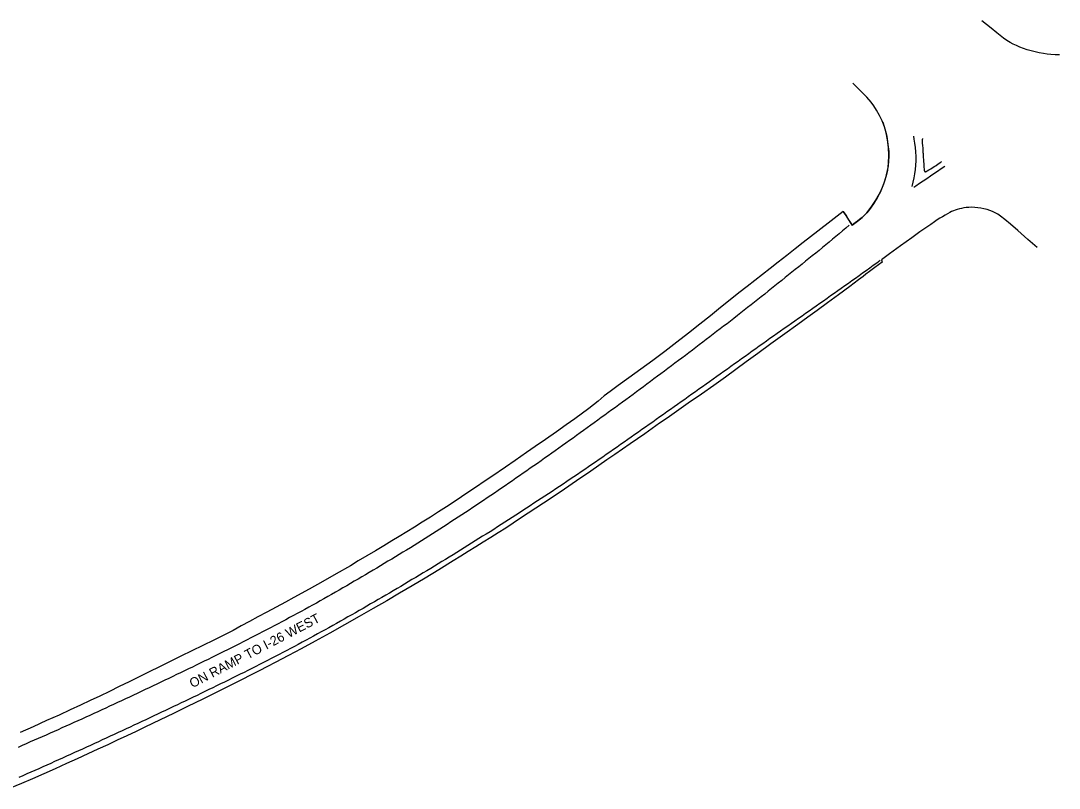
# Model space of a CAD drawing. Extents: x 1961683 to 1977751, y 798292 to 805767.
# Drawn here: x 1970784 to 1971379, y 802511 to 802951 of the extents above; entities that cross this region are included whole.
import ezdxf

# ---------------------------------------------------------------- set-up
doc = ezdxf.new("R2010")
doc.units = 0
for name, color, linetype in [('RD_EX_Conc', 7, 'Continuous'), ('RD_EX_Road', 7, 'Continuous'), ('RD_EX_Road_Paint', 7, 'Continuous'), ('RD_TX_RoadID', 7, 'Continuous')]:
    doc.layers.add(name, color=color, linetype=linetype)

msp = doc.modelspace()

# ---------------------------------------------------------------- linework, layer by layer
at = {"layer": 'RD_EX_Conc'}
msp.add_lwpolyline([(1971300.79, 802883.01), (1971300.74, 802882.82), (1971300.67, 802882.28), (1971300.67, 802881.48), (1971300.72, 802880.37), (1971300.82, 802878.97), (1971300.93, 802877.5), (1971301.05, 802876.05), (1971301.11, 802875.12), (1971301.12, 802874.54), (1971301.22, 802872.95), (1971301.41, 802870.36), (1971301.56, 802868.15), (1971301.67, 802866.55), (1971301.74, 802865.56), (1971301.79, 802865.1), (1971301.84, 802864.78), (1971301.91, 802864.53), (1971301.99, 802864.33), (1971302.04, 802864.25), (1971302.1, 802864.19), (1971302.16, 802864.13), (1971302.21, 802864.09), (1971302.28, 802864.05), (1971302.35, 802864.03), (1971302.45, 802864.03), (1971302.57, 802864.04), (1971302.71, 802864.07), (1971302.91, 802864.14), (1971303.55, 802864.46), (1971304.5, 802865.03), (1971305.65, 802865.75), (1971306.91, 802866.57), (1971307.88, 802867.2), (1971308.6, 802867.67), (1971309.72, 802868.46), (1971311.27, 802869.57), (1971311.66, 802869.84)], dxfattribs=at)
at = {"layer": 'RD_EX_Road'}
for points in [[(1971379.24, 802930.98), (1971376.83, 802931.04), (1971374.46, 802931.18), (1971372.29, 802931.4), (1971370.11, 802931.73), (1971367.74, 802932.19), (1971365.33, 802932.74), (1971363.04, 802933.33), (1971360.82, 802933.99), (1971358.63, 802934.73), (1971356.56, 802935.53), (1971354.67, 802936.33), (1971352.85, 802937.2), (1971350.98, 802938.21), (1971349.11, 802939.36), (1971347.26, 802940.66), (1971345.37, 802942.1), (1971343.34, 802943.69), (1971340.17, 802946.25), (1971334.83, 802950.59)], [(1971255.41, 802841.16), (1971257.06, 802838.99), (1971258.68, 802836.32), (1971260.51, 802833.29), (1971263.59, 802835.69), (1971266.19, 802837.84), (1971268.87, 802840.52), (1971271.41, 802843.68), (1971274.17, 802847.67), (1971276.68, 802852.22), (1971278.67, 802857.01), (1971280.02, 802861.34), (1971280.88, 802864.98), (1971281.4, 802868.88), (1971281.56, 802873.45), (1971281.32, 802877.95), (1971280.72, 802882.32), (1971279.93, 802886.26), (1971278.98, 802889.7), (1971277.63, 802893.22), (1971276.12, 802896.28), (1971274.52, 802899.26), (1971272.97, 802901.88), (1971271.32, 802904), (1971268.85, 802906.71), (1971263.87, 802911.8), (1971260.98, 802914.75)], [(1971278, 802892.43), (1971278.82, 802890), (1971279.62, 802887.26), (1971280.32, 802884.33), (1971280.86, 802881.34), (1971281.23, 802878.39), (1971281.45, 802875.53), (1971281.51, 802872.77), (1971281.39, 802870.07), (1971281.1, 802867.4), (1971280.65, 802864.76), (1971280.08, 802862.2), (1971279.42, 802859.76), (1971278.66, 802857.39), (1971277.75, 802854.98), (1971276.55, 802852.28), (1971274.89, 802849.05), (1971272.82, 802845.54), (1971270.42, 802842.42), (1971268.87, 802840.52), (1971267.65, 802839.2), (1971266.19, 802837.84), (1971264.75, 802836.61), (1971263.59, 802835.69), (1971262.31, 802834.71), (1971260.51, 802833.29), (1971257.06, 802838.99), (1971255.41, 802841.16), (1971248.48, 802835.94), (1971240.82, 802830.01), (1971236.7, 802826.78), (1971232.35, 802823.36), (1971227.79, 802819.77), (1971223, 802816), (1971218.19, 802812.21), (1971213.55, 802808.57), (1971209.08, 802805.08), (1971204.78, 802801.73), (1971200.4, 802798.3), (1971195.65, 802794.55), (1971190.56, 802790.48), (1971185.11, 802786.09), (1971179.32, 802781.44), (1971173.2, 802776.58), (1971166.76, 802771.51), (1971160, 802766.24), (1971153.09, 802760.92), (1971146.22, 802755.75), (1971139.38, 802750.72), (1971132.58, 802745.83), (1971126.5, 802741.46), (1971121.79, 802738.01), (1971118.46, 802735.47), (1971114.92, 802732.46), (1971109.64, 802728.3), (1971101.63, 802722.36), (1971096.66, 802718.8), (1971091.07, 802714.85), (1971084.86, 802710.53), (1971078.87, 802706.39), (1971073.98, 802703), (1971067.46, 802698.48), (1971061.95, 802694.69), (1971054.06, 802689.36), (1971049.57, 802686.34), (1971045.17, 802683.38), (1971040.85, 802680.47), (1971036.62, 802677.62), (1971032.36, 802674.78), (1971027.98, 802671.9), (1971023.47, 802668.97), (1971018.84, 802666.01), (1971014.2, 802663.08), (1971009.67, 802660.25), (1971005.27, 802657.53), (1971000.98, 802654.91), (1970996.65, 802652.29), (1970992.11, 802649.55), (1970987.36, 802646.71), (1970982.41, 802643.75), (1970977.51, 802640.84), (1970972.95, 802638.14), (1970964.83, 802633.38), (1970957.24, 802629.03), (1970949.38, 802624.65), (1970940.64, 802619.88), (1970935.71, 802617.22), (1970930.42, 802614.38), (1970925.06, 802611.5), (1970919.96, 802608.75), (1970915.1, 802606.11), (1970910.48, 802603.6), (1970905.74, 802601.06), (1970900.5, 802598.35), (1970894.75, 802595.46), (1970888.51, 802592.4), (1970882.07, 802589.28), (1970875.78, 802586.2), (1970869.62, 802583.17), (1970863.6, 802580.19), (1970857.69, 802577.26), (1970851.86, 802574.38), (1970846.12, 802571.56), (1970840.46, 802568.79), (1970834.86, 802566.08), (1970829.3, 802563.4), (1970823.77, 802560.77), (1970818.27, 802558.17), (1970812.46, 802555.47), (1970806, 802552.5), (1970798.89, 802549.28), (1970791.13, 802545.79), (1970783.74, 802542.5)], [(1971366.46, 802820.56), (1971361.23, 802825.21), (1971355.45, 802830.32), (1971351.3, 802833.95), (1971348, 802836.69), (1971345.59, 802838.5), (1971343.94, 802839.6), (1971342.93, 802840.24), (1971342.07, 802840.68), (1971340.9, 802841.23), (1971339.46, 802841.8), (1971337.8, 802842.34), (1971336.05, 802842.81), (1971334.34, 802843.15), (1971332.6, 802843.4), (1971330.78, 802843.56), (1971328.98, 802843.61), (1971327.3, 802843.56), (1971325.76, 802843.42), (1971324.43, 802843.25), (1971323.2, 802843.03), (1971321.97, 802842.75), (1971320.78, 802842.43), (1971319.63, 802842.05), (1971318.55, 802841.62), (1971317.52, 802841.13), (1971316.44, 802840.56), (1971315.17, 802839.89), (1971313.75, 802839.12), (1971312.22, 802838.25), (1971310.71, 802837.34), (1971309.32, 802836.43), (1971307.72, 802835.33), (1971305.53, 802833.85), (1971302.75, 802831.92), (1971299.34, 802829.48), (1971294.72, 802826.17), (1971288.3, 802821.6), (1971281.91, 802816.99), (1971277.33, 802813.57), (1971277.64, 802812.13)], [(1971277.64, 802812.13), (1971273.49, 802809.08), (1971270.49, 802806.84), (1971268.34, 802805.2), (1971266.76, 802803.98), (1971264.21, 802802.02), (1971259.13, 802798.19), (1971252.78, 802793.45), (1971246.39, 802788.79), (1971240.37, 802784.41), (1971235.14, 802780.55), (1971229.44, 802776.36), (1971221.99, 802771.02), (1971213.96, 802765.29), (1971206.51, 802759.88), (1971199.77, 802754.93), (1971193.84, 802750.54), (1971187.95, 802746.24), (1971181.33, 802741.54), (1971174.14, 802736.52), (1971166.54, 802731.24), (1971158.56, 802725.68), (1971154.42, 802722.78), (1971150.19, 802719.81), (1971145.92, 802716.81), (1971141.67, 802713.83), (1971137.44, 802710.87), (1971133.23, 802707.94), (1971128.96, 802704.97), (1971124.55, 802701.91), (1971119.99, 802698.76), (1971115.28, 802695.52), (1971110.68, 802692.36), (1971102.6, 802686.8), (1971095.67, 802682.04), (1971087.94, 802676.85), (1971083.64, 802674.01), (1971079.23, 802671.1), (1971074.87, 802668.22), (1971070.55, 802665.37), (1971066.28, 802662.54), (1971062.03, 802659.74), (1971057.75, 802656.98), (1971053.45, 802654.26), (1971049.13, 802651.57), (1971044.81, 802648.89), (1971040.51, 802646.21), (1971036.22, 802643.52), (1971031.95, 802640.83), (1971023.69, 802635.67), (1971015.91, 802630.99), (1971008.46, 802626.61), (1971001.16, 802622.34), (1970993.78, 802618.06), (1970986.08, 802613.61), (1970978.05, 802609), (1970969.69, 802604.22), (1970961.21, 802599.42), (1970952.8, 802594.78), (1970944.82, 802590.46), (1970937.58, 802586.63), (1970929.94, 802582.66), (1970925.54, 802580.39), (1970920.74, 802577.91), (1970915.81, 802575.38), (1970911, 802572.92), (1970906.31, 802570.54), (1970901.75, 802568.23), (1970897.26, 802565.98), (1970888.37, 802561.57), (1970879.68, 802557.31), (1970871.65, 802553.4), (1970864.06, 802549.73), (1970855.16, 802545.49), (1970850.12, 802543.1), (1970844.82, 802540.61), (1970839.41, 802538.07), (1970833.89, 802535.5), (1970828.26, 802532.88), (1970822.48, 802530.2), (1970816.48, 802527.45), (1970810.28, 802524.62), (1970803.87, 802521.72), (1970797.37, 802518.81), (1970790.9, 802515.98), (1970784.48, 802513.21), (1970778.09, 802510.52)]]:
    msp.add_lwpolyline(points, dxfattribs=at)
at = {"layer": 'RD_EX_Road_Paint'}
for points in [[(1971294.99, 802855.53), (1971295.51, 802857.98), (1971295.99, 802860.43), (1971296.37, 802862.9), (1971296.75, 802865.37), (1971297.01, 802867.86), (1971297.24, 802870.35), (1971297.15, 802872.85), (1971297.06, 802875.34), (1971296.81, 802877.83), (1971296.45, 802880.31), (1971296.08, 802882.78), (1971295.85, 802884.38)], [(1971313.62, 802867.02), (1971311.55, 802865.62), (1971309.48, 802864.22), (1971307.41, 802862.83), (1971305.34, 802861.43), (1971303.27, 802860.03), (1971301.2, 802858.63), (1971299.13, 802857.23), (1971297.06, 802855.84), (1971295.87, 802855.03)], [(1971258.87, 802833.33), (1971256.96, 802831.72), (1971255.06, 802830.1), (1971253.15, 802828.49), (1971251.24, 802826.88), (1971249.32, 802825.28), (1971247.39, 802823.68), (1971245.46, 802822.09), (1971243.53, 802820.5), (1971241.59, 802818.93), (1971239.64, 802817.36), (1971237.69, 802815.8), (1971235.75, 802814.23), (1971233.8, 802812.67), (1971231.85, 802811.11), (1971229.9, 802809.54), (1971227.95, 802807.98), (1971226, 802806.41), (1971224.05, 802804.85), (1971222.1, 802803.29), (1971220.15, 802801.72), (1971218.2, 802800.16), (1971216.25, 802798.6), (1971214.3, 802797.03), (1971212.35, 802795.47), (1971210.4, 802793.91), (1971208.45, 802792.34), (1971206.5, 802790.78), (1971204.55, 802789.22), (1971202.6, 802787.66), (1971200.63, 802786.12), (1971198.66, 802784.58), (1971196.7, 802783.04), (1971194.73, 802781.5), (1971192.76, 802779.96), (1971190.79, 802778.42), (1971188.81, 802776.9), (1971186.82, 802775.39), (1971184.83, 802773.87), (1971182.84, 802772.36), (1971180.85, 802770.84), (1971178.87, 802769.32), (1971176.88, 802767.81), (1971174.9, 802766.29), (1971172.91, 802764.77), (1971170.93, 802763.25), (1971168.94, 802761.73), (1971166.95, 802760.22), (1971164.96, 802758.71), (1971162.96, 802757.21), (1971160.97, 802755.7), (1971158.98, 802754.2), (1971156.98, 802752.69), (1971154.98, 802751.19), (1971152.98, 802749.7), (1971150.97, 802748.21), (1971148.96, 802746.72), (1971146.96, 802745.23), (1971144.95, 802743.74), (1971142.94, 802742.25), (1971140.94, 802740.76), (1971138.94, 802739.27), (1971136.93, 802737.77), (1971134.93, 802736.27), (1971132.93, 802734.78), (1971130.91, 802733.31), (1971128.88, 802731.84), (1971126.86, 802730.38), (1971124.83, 802728.92), (1971122.8, 802727.46), (1971120.78, 802725.99), (1971118.75, 802724.53), (1971116.73, 802723.07), (1971114.71, 802721.59), (1971112.69, 802720.12), (1971110.67, 802718.65), (1971108.65, 802717.17), (1971106.63, 802715.7), (1971104.61, 802714.23), (1971102.58, 802712.77), (1971100.55, 802711.32), (1971098.52, 802709.86), (1971096.48, 802708.41), (1971094.45, 802706.95), (1971092.42, 802705.5), (1971090.39, 802704.05), (1971088.35, 802702.6), (1971086.31, 802701.14), (1971084.28, 802699.69), (1971082.24, 802698.25), (1971080.2, 802696.81), (1971078.14, 802695.39), (1971076.08, 802693.97), (1971074.03, 802692.55), (1971071.97, 802691.13), (1971069.92, 802689.71), (1971067.86, 802688.28), (1971065.81, 802686.86), (1971063.75, 802685.44), (1971061.7, 802684.01), (1971059.64, 802682.59), (1971057.58, 802681.18), (1971055.52, 802679.77), (1971053.45, 802678.37), (1971051.38, 802676.96), (1971049.31, 802675.56), (1971047.23, 802674.18), (1971045.15, 802672.79), (1971043.07, 802671.41), (1971040.99, 802670.03), (1971038.9, 802668.66), (1971036.81, 802667.29), (1971034.71, 802665.92), (1971032.62, 802664.55), (1971030.53, 802663.19), (1971028.43, 802661.83), (1971026.33, 802660.47), (1971024.23, 802659.12), (1971022.13, 802657.77), (1971020.02, 802656.43), (1971017.91, 802655.08), (1971015.8, 802653.74), (1971013.69, 802652.4), (1971011.58, 802651.07), (1971009.45, 802649.76), (1971007.33, 802648.44), (1971005.2, 802647.12), (1971003.08, 802645.81), (1971000.95, 802644.5), (1970998.81, 802643.21), (1970996.66, 802641.93), (1970994.52, 802640.64), (1970992.38, 802639.35), (1970990.24, 802638.07), (1970988.09, 802636.78), (1970985.95, 802635.5), (1970983.8, 802634.22), (1970981.66, 802632.93), (1970979.5, 802631.67), (1970977.34, 802630.41), (1970975.18, 802629.16), (1970973.01, 802627.91), (1970970.85, 802626.66), (1970968.69, 802625.41), (1970966.52, 802624.15), (1970964.36, 802622.9), (1970962.2, 802621.65), (1970960.03, 802620.41), (1970957.85, 802619.18), (1970955.67, 802617.95), (1970953.5, 802616.73), (1970951.32, 802615.5), (1970949.14, 802614.27), (1970946.96, 802613.06), (1970944.76, 802611.86), (1970942.55, 802610.69), (1970940.35, 802609.51), (1970938.15, 802608.33), (1970935.94, 802607.15), (1970933.74, 802605.98), (1970931.53, 802604.8), (1970929.32, 802603.64), (1970927.1, 802602.47), (1970924.89, 802601.31), (1970922.68, 802600.15), (1970920.46, 802599.01), (1970918.23, 802597.86), (1970916.01, 802596.72), (1970913.79, 802595.57), (1970911.56, 802594.43), (1970909.34, 802593.3), (1970907.1, 802592.18), (1970904.86, 802591.06), (1970902.62, 802589.95), (1970900.39, 802588.84), (1970898.15, 802587.73), (1970895.9, 802586.62), (1970893.66, 802585.52), (1970891.42, 802584.41), (1970889.17, 802583.31), (1970886.93, 802582.21), (1970884.69, 802581.11), (1970882.44, 802580.01), (1970880.19, 802578.93), (1970877.93, 802577.86), (1970875.67, 802576.78), (1970873.42, 802575.71), (1970871.16, 802574.62), (1970868.91, 802573.54), (1970866.66, 802572.46), (1970864.4, 802571.38), (1970862.15, 802570.29), (1970859.89, 802569.21), (1970857.64, 802568.13), (1970855.38, 802567.05), (1970853.12, 802565.98), (1970850.87, 802564.91), (1970848.61, 802563.84), (1970846.35, 802562.77), (1970844.08, 802561.71), (1970841.81, 802560.66), (1970839.55, 802559.61), (1970837.28, 802558.57), (1970835.01, 802557.52), (1970832.74, 802556.47), (1970830.47, 802555.42), (1970828.19, 802554.38), (1970825.92, 802553.34), (1970823.65, 802552.3), (1970821.37, 802551.26), (1970819.1, 802550.22), (1970816.82, 802549.19), (1970814.55, 802548.16), (1970812.27, 802547.13), (1970809.99, 802546.11), (1970807.71, 802545.08), (1970805.43, 802544.06), (1970803.14, 802543.04), (1970800.85, 802542.04), (1970798.56, 802541.04), (1970796.27, 802540.04), (1970793.97, 802539.05), (1970791.68, 802538.05), (1970789.39, 802537.04), (1970787.11, 802536.03), (1970784.83, 802535), (1970782.55, 802533.97)], [(1971276.65, 802813.1), (1971274.62, 802811.64), (1971272.59, 802810.18), (1971270.56, 802808.72), (1971268.53, 802807.26), (1971266.5, 802805.8), (1971264.48, 802804.35), (1971262.45, 802802.89), (1971260.41, 802801.43), (1971258.37, 802799.99), (1971256.33, 802798.54), (1971254.29, 802797.1), (1971252.26, 802795.65), (1971250.22, 802794.21), (1971248.17, 802792.77), (1971246.12, 802791.34), (1971244.08, 802789.9), (1971242.03, 802788.47), (1971239.98, 802787.03), (1971237.94, 802785.6), (1971235.89, 802784.16), (1971233.85, 802782.72), (1971231.8, 802781.28), (1971229.76, 802779.84), (1971227.72, 802778.4), (1971225.67, 802776.97), (1971223.63, 802775.53), (1971221.59, 802774.09), (1971219.54, 802772.65), (1971217.5, 802771.21), (1971215.46, 802769.76), (1971213.43, 802768.31), (1971211.39, 802766.86), (1971209.36, 802765.41), (1971207.32, 802763.96), (1971205.29, 802762.51), (1971203.25, 802761.06), (1971201.22, 802759.61), (1971199.18, 802758.16), (1971197.15, 802756.71), (1971195.11, 802755.25), (1971193.08, 802753.8), (1971191.04, 802752.35), (1971189.01, 802750.9), (1971186.98, 802749.44), (1971184.94, 802747.99), (1971182.91, 802746.54), (1971180.87, 802745.09), (1971178.84, 802743.64), (1971176.81, 802742.18), (1971174.77, 802740.73), (1971172.73, 802739.29), (1971170.69, 802737.84), (1971168.65, 802736.4), (1971166.61, 802734.96), (1971164.57, 802733.51), (1971162.53, 802732.07), (1971160.49, 802730.62), (1971158.45, 802729.18), (1971156.41, 802727.73), (1971154.37, 802726.29), (1971152.33, 802724.85), (1971150.29, 802723.4), (1971148.25, 802721.96), (1971146.21, 802720.52), (1971144.17, 802719.08), (1971142.12, 802717.63), (1971140.08, 802716.19), (1971138.04, 802714.75), (1971136, 802713.31), (1971133.95, 802711.87), (1971131.91, 802710.43), (1971129.87, 802708.99), (1971127.83, 802707.55), (1971125.78, 802706.12), (1971123.73, 802704.68), (1971121.69, 802703.25), (1971119.64, 802701.81), (1971117.6, 802700.38), (1971115.54, 802698.96), (1971113.48, 802697.55), (1971111.41, 802696.13), (1971109.35, 802694.72), (1971107.29, 802693.31), (1971105.23, 802691.9), (1971103.16, 802690.49), (1971101.09, 802689.09), (1971099.01, 802687.7), (1971096.94, 802686.31), (1971094.86, 802684.92), (1971092.78, 802683.53), (1971090.71, 802682.14), (1971088.63, 802680.75), (1971086.55, 802679.36), (1971084.46, 802677.99), (1971082.36, 802676.63), (1971080.27, 802675.27), (1971078.17, 802673.9), (1971076.08, 802672.54), (1971073.99, 802671.18), (1971071.89, 802669.81), (1971069.8, 802668.45), (1971067.69, 802667.1), (1971065.59, 802665.74), (1971063.49, 802664.39), (1971061.39, 802663.03), (1971059.29, 802661.68), (1971057.19, 802660.33), (1971055.09, 802658.97), (1971052.98, 802657.63), (1971050.87, 802656.3), (1971048.75, 802654.97), (1971046.64, 802653.63), (1971044.52, 802652.3), (1971042.4, 802650.98), (1971040.28, 802649.66), (1971038.16, 802648.34), (1971036.04, 802647.02), (1971033.92, 802645.7), (1971031.79, 802644.38), (1971029.66, 802643.08), (1971027.53, 802641.77), (1971025.4, 802640.47), (1971023.27, 802639.16), (1971021.13, 802637.85), (1971019, 802636.56), (1971016.85, 802635.27), (1971014.71, 802633.98), (1971012.57, 802632.7), (1971010.42, 802631.41), (1971008.28, 802630.13), (1971006.14, 802628.84), (1971003.99, 802627.57), (1971001.84, 802626.29), (1970999.69, 802625.01), (1970997.54, 802623.74), (1970995.39, 802622.46), (1970993.24, 802621.19), (1970991.08, 802619.93), (1970988.92, 802618.68), (1970986.76, 802617.43), (1970984.59, 802616.17), (1970982.43, 802614.92), (1970980.26, 802613.67), (1970978.09, 802612.43), (1970975.92, 802611.19), (1970973.75, 802609.95), (1970971.58, 802608.71), (1970969.41, 802607.47), (1970967.23, 802606.25), (1970965.05, 802605.03), (1970962.87, 802603.81), (1970960.69, 802602.59), (1970958.51, 802601.37), (1970956.31, 802600.17), (1970954.12, 802598.97), (1970951.93, 802597.77), (1970949.73, 802596.58), (1970947.54, 802595.38), (1970945.33, 802594.2), (1970943.13, 802593.02), (1970940.93, 802591.84), (1970938.72, 802590.66), (1970936.51, 802589.49), (1970934.29, 802588.34), (1970932.08, 802587.19), (1970929.86, 802586.04), (1970927.64, 802584.89), (1970925.42, 802583.74), (1970923.19, 802582.6), (1970920.97, 802581.46), (1970918.74, 802580.32), (1970916.52, 802579.18), (1970914.28, 802578.06), (1970912.04, 802576.95), (1970909.8, 802575.84), (1970907.56, 802574.73), (1970905.32, 802573.62), (1970903.08, 802572.51), (1970900.84, 802571.41), (1970898.59, 802570.32), (1970896.34, 802569.23), (1970894.09, 802568.14), (1970891.84, 802567.05), (1970889.59, 802565.96), (1970887.34, 802564.87), (1970885.09, 802563.78), (1970882.84, 802562.7), (1970880.58, 802561.62), (1970878.32, 802560.54), (1970876.07, 802559.47), (1970873.81, 802558.39), (1970871.55, 802557.32), (1970869.3, 802556.24), (1970867.04, 802555.17), (1970864.78, 802554.09), (1970862.52, 802553.02), (1970860.26, 802551.96), (1970858, 802550.89), (1970855.74, 802549.83), (1970853.48, 802548.76), (1970851.21, 802547.7), (1970848.95, 802546.64), (1970846.69, 802545.57), (1970844.43, 802544.51), (1970842.16, 802543.45), (1970839.89, 802542.4), (1970837.62, 802541.35), (1970835.35, 802540.31), (1970833.08, 802539.26), (1970830.81, 802538.21), (1970828.54, 802537.16), (1970826.27, 802536.12), (1970824, 802535.08), (1970821.72, 802534.04), (1970819.45, 802533.01), (1970817.17, 802531.98), (1970814.89, 802530.94), (1970812.62, 802529.91), (1970810.34, 802528.87), (1970808.06, 802527.85), (1970805.78, 802526.83), (1970803.5, 802525.81), (1970801.22, 802524.79), (1970798.93, 802523.77), (1970796.65, 802522.75), (1970794.37, 802521.73), (1970792.08, 802520.71), (1970789.79, 802519.71), (1970787.5, 802518.72), (1970785.2, 802517.72), (1970782.91, 802516.73)]]:
    msp.add_lwpolyline(points, dxfattribs=at)

# ---------------------------------------------------------------- texts
at = {"layer": 'RD_TX_RoadID'}
msp.add_text('ON RAMP TO I-26 WEST', height=5.4, rotation=27.51001, dxfattribs=at).set_placement((1970882.48, 802567.86))

doc.saveas('drawing.dxf')
